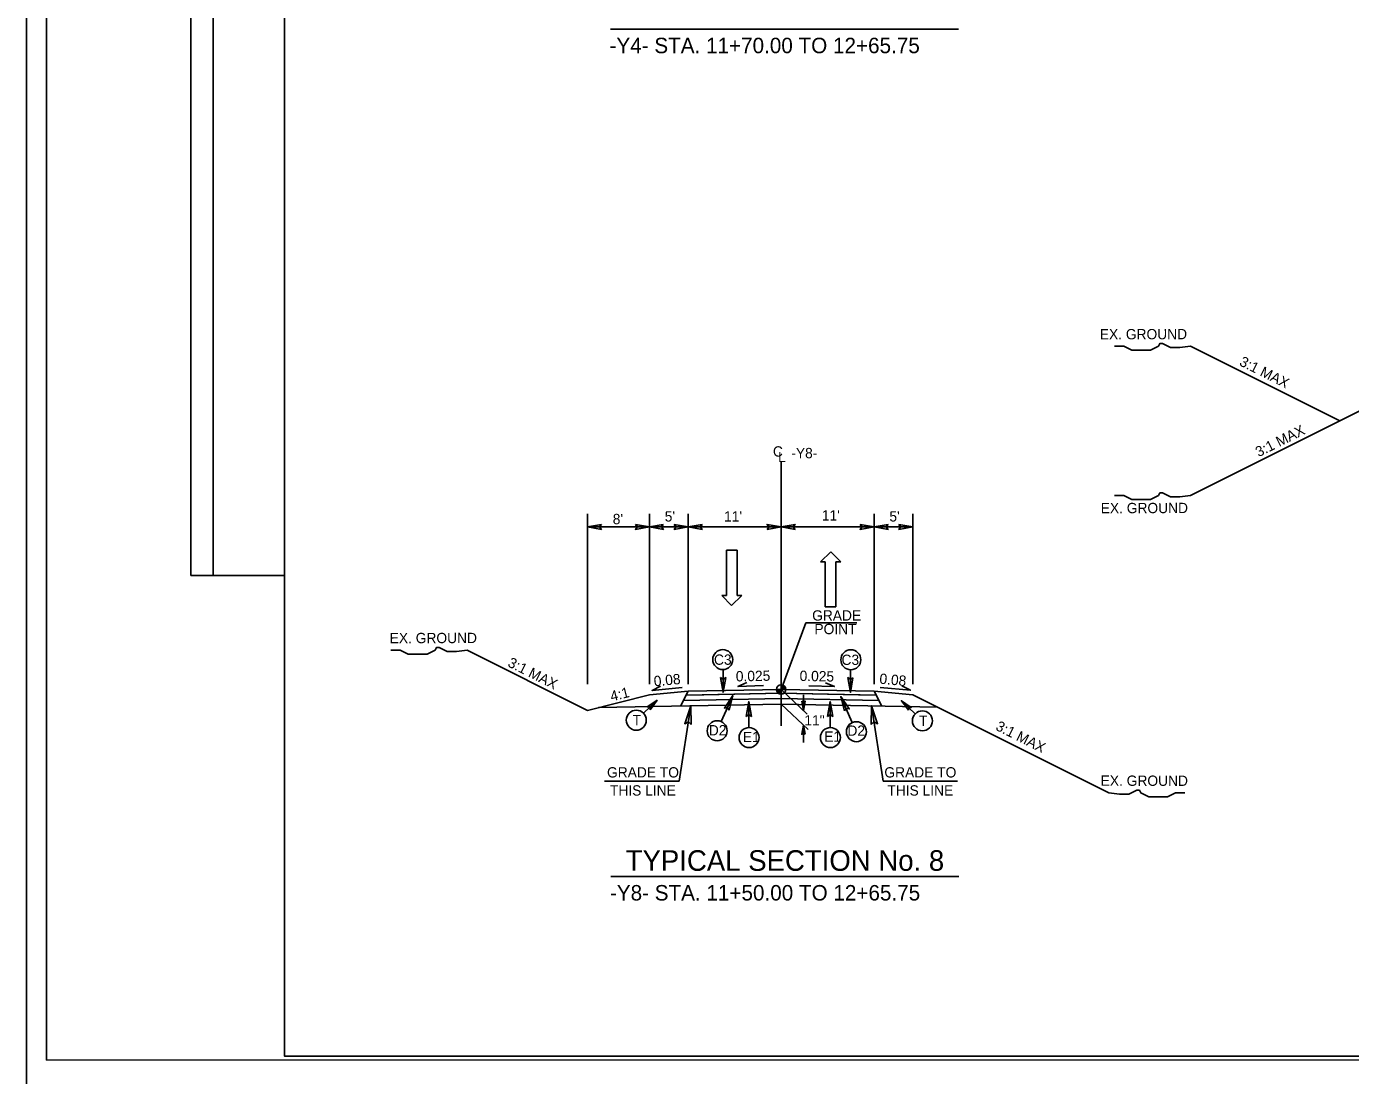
# Model space of a CAD drawing. Extents: x 2320980 to 2456309, y 595047 to 606177.
# Drawn here: x 2455708.8 to 2455879.7, y 596305.6 to 596440.9 of the extents above; entities that cross this region are included whole.
import ezdxf

# ---------------------------------------------------------------- set-up
doc = ezdxf.new("R2010")
doc.units = 0
for name, color, linetype in [('Old_Level_1', 7, 'Continuous'), ('Old_Level_11', 7, 'Continuous'), ('Old_Level_2', 7, 'Continuous'), ('Old_Level_20', 7, 'Continuous'), ('Old_Level_21', 7, 'Continuous'), ('Old_Level_3', 7, 'Continuous'), ('Prop Dimension', 7, 'Continuous'), ('Prop Dimension Text', 7, 'Continuous'), ('Prop Lane Arrow CELL', 7, 'Continuous'), ('Prop Terminator CELL', 7, 'Continuous'), ('Sheet Block Revision CELL', 7, 'Continuous'), ('Sheet Cutting Line CELL', 7, 'Continuous'), ('Sheet Plan CELL', 7, 'Continuous'), ('Sheet Plot Border Inside CELL', 7, 'Continuous'), ('Sheet Plot Border Outside CELL', 7, 'Continuous'), ('Typical Grade Point Symbol CELL', 7, 'Continuous'), ('Typical ID Circle CELL', 7, 'Continuous'), ('Typical Pavement Slope CELL', 7, 'Continuous'), ('Typical Pavement Slope Information CELL', 7, 'Continuous'), ('Typical Slope Point Local CELL', 7, 'Continuous'), ('Typical Terminator CELL', 7, 'Continuous')]:
    doc.layers.add(name, color=color, linetype=linetype)

msp = doc.modelspace()

# ---------------------------------------------------------------- linework, layer by layer
at = {"layer": 'Old_Level_1'}
for p, q in [((2455806.21, 596355.38), (2455809.42, 596363.99)), ((2455809.42, 596363.99), (2455815.97, 596363.99)), ((2455794.22, 596355.14), (2455789.22, 596354.67)), ((2455818.22, 596355.14), (2455823.22, 596354.67))]:
    msp.add_line(p, q, dxfattribs=at)
at = {"layer": 'Old_Level_11'}
for points in [[(2455794.6, 596350.84), (2455794.57, 596353.27), (2455793.77, 596350.95), (2455794.24, 596351.19)], [(2455817.83, 596350.84), (2455817.86, 596353.27), (2455818.66, 596350.95), (2455818.19, 596351.19)]]:
    msp.add_lwpolyline(points, close=True, dxfattribs=at)
at = {"layer": 'Old_Level_21'}
for p, q in [((2455781.22, 596356.06), (2455781.22, 596378.03)), ((2455789.22, 596356.06), (2455789.22, 596378.03)), ((2455794.22, 596356.06), (2455794.22, 596378.03)), ((2455818.22, 596356.06), (2455818.22, 596378.03)), ((2455823.22, 596356.06), (2455823.22, 596378.03)), ((2455781.22, 596376.34), (2455789.22, 596376.34)), ((2455789.22, 596376.34), (2455794.22, 596376.34)), ((2455794.22, 596376.34), (2455806.22, 596376.34)), ((2455818.22, 596376.34), (2455806.22, 596376.34)), ((2455818.22, 596376.34), (2455823.22, 596376.34)), ((2455793.05, 596343.55), (2455794.57, 596353.27)), ((2455819.38, 596343.55), (2455817.86, 596353.27)), ((2455793.05, 596343.55), (2455783.43, 596343.55)), ((2455819.38, 596343.55), (2455829, 596343.55))]:
    msp.add_line(p, q, dxfattribs=at)
at = {"layer": 'Old_Level_3'}
for p, q in [((2455784.21, 596440.56), (2455829.13, 596440.56)), ((2455806.22, 596354.9), (2455793.96, 596354.66)), ((2455806.22, 596354.9), (2455818.47, 596354.66)), ((2455784.25, 596331.25), (2455829.17, 596331.25))]:
    msp.add_line(p, q, dxfattribs=at)
at = {"layer": 'Prop Dimension'}
for p, q in [((2455806.22, 596355.38), (2455809.59, 596352.2)), ((2455809.09, 596354.67), (2455809.09, 596352.67)), ((2455806.21, 596353.5), (2455809.72, 596350.2)), ((2455809.09, 596350.79), (2455809.09, 596348.54))]:
    msp.add_line(p, q, dxfattribs=at)
at = {"layer": 'Prop Dimension Text'}
for p, q in [((2455806.22, 596350.68), (2455806.22, 596384.7)), ((2455788.45, 596352.3), (2455790.21, 596353.99)), ((2455823.51, 596352.23), (2455821.75, 596353.91))]:
    msp.add_line(p, q, dxfattribs=at)
for points in [[(2455793.44, 596355.63), (2455789.55, 596355.25), (2455790.65, 596355.82)], [(2455803.96, 596355.87), (2455800.64, 596355.78), (2455801.78, 596356.27)], [(2455809.77, 596355.85), (2455813.09, 596355.76), (2455811.96, 596356.24)], [(2455819, 596355.64), (2455822.9, 596355.27), (2455821.8, 596355.83)]]:
    msp.add_lwpolyline(points, dxfattribs=at)
for centre in [(2455798.68, 596359.23), (2455815.21, 596359.21), (2455787.52, 596351.41), (2455797.96, 596350.05), (2455815.93, 596349.93), (2455824.45, 596351.33), (2455802.07, 596349.17), (2455812.57, 596349.17)]:
    msp.add_circle(centre, 1.29, dxfattribs=at)
at = {"layer": 'Prop Lane Arrow CELL'}
for p, q in [((2455799.16, 596373.33), (2455799.16, 596367.51)), ((2455800.54, 596373.33), (2455799.16, 596373.33)), ((2455800.54, 596367.51), (2455800.54, 596373.33)), ((2455812.61, 596373.15), (2455811.28, 596371.84)), ((2455811.28, 596371.84), (2455811.91, 596371.84)), ((2455811.91, 596371.84), (2455811.91, 596366.03)), ((2455813.9, 596371.84), (2455812.61, 596373.15)), ((2455813.28, 596366.03), (2455813.28, 596371.84)), ((2455813.28, 596371.84), (2455813.9, 596371.84)), ((2455799.16, 596367.51), (2455798.54, 596367.51)), ((2455798.54, 596367.51), (2455799.83, 596366.2)), ((2455799.83, 596366.2), (2455801.16, 596367.51)), ((2455801.16, 596367.51), (2455800.54, 596367.51)), ((2455811.91, 596366.03), (2455813.28, 596366.03))]:
    msp.add_line(p, q, dxfattribs=at)
at = {"layer": 'Prop Terminator CELL'}
for points in [[(2455808.89, 596353.87), (2455809.09, 596352.67), (2455809.3, 596353.87), (2455809.09, 596353.72)], [(2455809.3, 596349.6), (2455809.09, 596350.79), (2455808.88, 596349.59), (2455809.09, 596349.74)]]:
    msp.add_lwpolyline(points, close=True, dxfattribs=at)
at = {"layer": 'Sheet Block Revision CELL'}
msp.add_line((2455732.91, 596370.08), (2455732.91, 596528.2), dxfattribs=at)
msp.add_lwpolyline([(2455730, 596370.07), (2455730, 596528.2), (2455742.11, 596528.21), (2455742.11, 596370.08)], close=True, dxfattribs=at)
at = {"layer": 'Sheet Cutting Line CELL'}
msp.add_line((2455708.81, 596541.57), (2455708.81, 596322.57), dxfattribs=at)
at = {"layer": 'Sheet Plan CELL'}
for points in [[(2456042.11, 596518.08), (2455742.1, 596518.08), (2455742.1, 596308.08), (2456042.11, 596308.08)], [(2455742.1, 596308.08), (2455742.1, 596518.07), (2456002.1, 596518.08), (2456002.1, 596488.07), (2456042.11, 596488.06), (2456042.11, 596308.08)]]:
    msp.add_lwpolyline(points, close=True, dxfattribs=at)
at = {"layer": 'Sheet Plot Border Inside CELL'}
msp.add_lwpolyline([(2455711.41, 596307.57), (2456044.6, 596307.58), (2456044.61, 596518.57), (2455711.41, 596518.57)], close=True, dxfattribs=at)
at = {"layer": 'Sheet Plot Border Outside CELL'}
msp.add_lwpolyline([(2455708.81, 596303.57), (2456045.51, 596303.57), (2456045.51, 596522.57), (2455708.81, 596522.57)], close=True, dxfattribs=at)
at = {"layer": 'Typical Grade Point Symbol CELL'}
for p, q in [((2455805.62, 596355.38), (2455806.21, 596355.38)), ((2455806.21, 596355.38), (2455806.21, 596355.98)), ((2455806.81, 596355.38), (2455806.21, 596355.38)), ((2455806.21, 596354.79), (2455806.21, 596355.38)), ((2455806.21, 596355.38), (2455806.21, 596354.79))]:
    msp.add_line(p, q, dxfattribs=at)
for points in [[(2455805.62, 596355.38), (2455805.62, 596355.32)], [(2455805.63, 596355.38), (2455805.63, 596355.25)], [(2455805.65, 596355.38), (2455805.65, 596355.2)], [(2455805.66, 596355.38), (2455805.66, 596355.17)], [(2455805.67, 596355.38), (2455805.67, 596355.14)], [(2455805.68, 596355.38), (2455805.68, 596355.12)], [(2455805.69, 596355.38), (2455805.69, 596355.09)], [(2455805.7, 596355.38), (2455805.7, 596355.07)], [(2455805.72, 596355.38), (2455805.72, 596355.05)], [(2455805.73, 596355.38), (2455805.73, 596355.04)], [(2455805.74, 596355.38), (2455805.74, 596355.02)], [(2455805.75, 596355.38), (2455805.75, 596355.01)], [(2455805.76, 596355.38), (2455805.76, 596354.99)], [(2455805.78, 596355.38), (2455805.78, 596354.98)], [(2455805.79, 596355.38), (2455805.79, 596354.97)], [(2455805.8, 596355.38), (2455805.8, 596354.95)], [(2455805.81, 596355.38), (2455805.81, 596354.94)], [(2455805.82, 596355.38), (2455805.82, 596354.93)], [(2455805.84, 596355.38), (2455805.84, 596354.92)], [(2455805.85, 596355.38), (2455805.85, 596354.91)], [(2455805.86, 596355.38), (2455805.86, 596354.9)], [(2455805.87, 596355.38), (2455805.87, 596354.9)], [(2455805.88, 596355.38), (2455805.88, 596354.89)], [(2455805.9, 596355.38), (2455805.9, 596354.88)], [(2455805.91, 596355.38), (2455805.91, 596354.87)], [(2455805.92, 596355.38), (2455805.92, 596354.86)], [(2455805.93, 596355.38), (2455805.93, 596354.86)], [(2455805.94, 596355.38), (2455805.94, 596354.85)], [(2455805.95, 596355.38), (2455805.95, 596354.85)], [(2455805.97, 596355.38), (2455805.97, 596354.84)], [(2455805.98, 596355.38), (2455805.98, 596354.84)], [(2455805.99, 596355.38), (2455805.99, 596354.83)], [(2455806, 596355.38), (2455806, 596354.83)], [(2455806.01, 596355.38), (2455806.01, 596354.82)], [(2455806.03, 596355.38), (2455806.03, 596354.82)], [(2455806.04, 596355.38), (2455806.04, 596354.81)], [(2455806.05, 596355.38), (2455806.05, 596354.81)], [(2455806.06, 596355.38), (2455806.06, 596354.81)], [(2455806.07, 596355.38), (2455806.07, 596354.8)], [(2455806.09, 596355.38), (2455806.09, 596354.8)], [(2455806.1, 596355.38), (2455806.1, 596354.8)], [(2455806.11, 596355.38), (2455806.11, 596354.8)], [(2455806.12, 596355.38), (2455806.12, 596354.79)], [(2455806.13, 596355.38), (2455806.13, 596354.79)], [(2455806.15, 596355.38), (2455806.15, 596354.79)], [(2455806.16, 596355.38), (2455806.16, 596354.79)], [(2455806.17, 596355.38), (2455806.17, 596354.79)], [(2455806.18, 596355.38), (2455806.18, 596354.79)], [(2455806.19, 596355.38), (2455806.19, 596354.79)], [(2455806.2, 596355.38), (2455806.2, 596354.79), (2455806.2, 596354.79)], [(2455806.22, 596355.98), (2455806.22, 596355.98), (2455806.22, 596355.38)], [(2455806.23, 596355.98), (2455806.23, 596355.38)], [(2455806.24, 596355.98), (2455806.24, 596355.38)], [(2455806.26, 596355.98), (2455806.26, 596355.38)], [(2455806.27, 596355.97), (2455806.27, 596355.38)], [(2455806.28, 596355.97), (2455806.28, 596355.38)], [(2455806.29, 596355.97), (2455806.29, 596355.38)], [(2455806.3, 596355.97), (2455806.3, 596355.38)], [(2455806.31, 596355.97), (2455806.31, 596355.38)], [(2455806.33, 596355.97), (2455806.33, 596355.38)], [(2455806.34, 596355.96), (2455806.34, 596355.38)], [(2455806.35, 596355.96), (2455806.35, 596355.38)], [(2455806.36, 596355.96), (2455806.36, 596355.38)], [(2455806.37, 596355.95), (2455806.37, 596355.38)], [(2455806.39, 596355.95), (2455806.39, 596355.38)], [(2455806.4, 596355.95), (2455806.4, 596355.38)], [(2455806.41, 596355.94), (2455806.41, 596355.38)], [(2455806.42, 596355.94), (2455806.42, 596355.38)], [(2455806.43, 596355.94), (2455806.43, 596355.38)], [(2455806.45, 596355.93), (2455806.45, 596355.38)], [(2455806.46, 596355.92), (2455806.46, 596355.38)], [(2455806.47, 596355.92), (2455806.47, 596355.38)], [(2455806.48, 596355.91), (2455806.48, 596355.38)], [(2455806.49, 596355.91), (2455806.49, 596355.38)], [(2455806.51, 596355.9), (2455806.51, 596355.38)], [(2455806.52, 596355.89), (2455806.52, 596355.38)], [(2455806.53, 596355.89), (2455806.53, 596355.38)], [(2455806.54, 596355.88), (2455806.54, 596355.38)], [(2455806.55, 596355.87), (2455806.55, 596355.38)], [(2455806.56, 596355.86), (2455806.56, 596355.38)], [(2455806.58, 596355.85), (2455806.58, 596355.38)], [(2455806.59, 596355.85), (2455806.59, 596355.38)], [(2455806.6, 596355.83), (2455806.6, 596355.38)], [(2455806.61, 596355.82), (2455806.61, 596355.38)], [(2455806.62, 596355.81), (2455806.62, 596355.38)], [(2455806.64, 596355.8), (2455806.64, 596355.38)], [(2455806.65, 596355.79), (2455806.65, 596355.38)], [(2455806.66, 596355.78), (2455806.66, 596355.38)], [(2455806.67, 596355.76), (2455806.67, 596355.38)], [(2455806.68, 596355.75), (2455806.68, 596355.38)], [(2455806.7, 596355.73), (2455806.7, 596355.38)], [(2455806.71, 596355.71), (2455806.71, 596355.38)], [(2455806.72, 596355.7), (2455806.72, 596355.38)], [(2455806.73, 596355.68), (2455806.73, 596355.38)], [(2455806.74, 596355.65), (2455806.74, 596355.38)], [(2455806.76, 596355.63), (2455806.76, 596355.38)], [(2455806.77, 596355.6), (2455806.77, 596355.38)], [(2455806.78, 596355.57), (2455806.78, 596355.38)], [(2455806.79, 596355.53), (2455806.79, 596355.38)], [(2455806.8, 596355.47), (2455806.8, 596355.38)]]:
    msp.add_lwpolyline(points, dxfattribs=at)
msp.add_circle((2455806.21, 596355.38), 0.595, dxfattribs=at)
for start, end in [(179.9905, 269.9905), (359.9905, 89.9905)]:
    msp.add_arc((2455806.21, 596355.38), 0.595, start, end, dxfattribs=at)
at = {"layer": 'Typical ID Circle CELL'}
for p, q in [((2455798.73, 596357.95), (2455798.73, 596355.01)), ((2455815.16, 596357.94), (2455815.16, 596355)), ((2455798.48, 596351.24), (2455799.97, 596354.54)), ((2455802.04, 596350.47), (2455802.04, 596353.81)), ((2455812.54, 596350.47), (2455812.54, 596353.81)), ((2455815.4, 596351.12), (2455813.92, 596354.42))]:
    msp.add_line(p, q, dxfattribs=at)
at = {"layer": 'Typical Pavement Slope CELL'}
for p, q in [((2455793.23, 596353.24), (2455794.22, 596355.14)), ((2455793.96, 596354.66), (2455793.61, 596353.97)), ((2455794.22, 596355.14), (2455793.96, 596354.66)), ((2455793.96, 596354.66), (2455806.22, 596354.9)), ((2455796.22, 596354.7), (2455793.96, 596354.66)), ((2455806.22, 596355.38), (2455794.22, 596355.14)), ((2455806.22, 596355.38), (2455794.22, 596355.14)), ((2455806.22, 596354.9), (2455796.22, 596354.7)), ((2455806.22, 596355.38), (2455818.22, 596355.14)), ((2455806.22, 596355.38), (2455818.22, 596355.14)), ((2455806.22, 596354.9), (2455806.22, 596355.38)), ((2455806.22, 596354.9), (2455806.22, 596355.38)), ((2455818.47, 596354.66), (2455806.22, 596354.9)), ((2455806.22, 596354.9), (2455806.22, 596354.22)), ((2455806.22, 596354.22), (2455806.22, 596354.9)), ((2455818.22, 596355.14), (2455818.47, 596354.66)), ((2455819.2, 596353.24), (2455818.22, 596355.14)), ((2455818.82, 596353.97), (2455818.47, 596354.66)), ((2455806.22, 596353.5), (2455782.64, 596353.03)), ((2455806.22, 596354.22), (2455793.61, 596353.97)), ((2455793.61, 596353.97), (2455806.22, 596354.22)), ((2455806.22, 596354.22), (2455818.82, 596353.97)), ((2455806.22, 596354.22), (2455818.82, 596353.97)), ((2455806.22, 596353.5), (2455826.36, 596353.1))]:
    msp.add_line(p, q, dxfattribs=at)
msp.add_lwpolyline([(2455818.47, 596354.66), (2455816.22, 596354.7), (2455806.22, 596354.9)], dxfattribs=at)
at = {"layer": 'Typical Slope Point Local CELL'}
for p, q in [((2455878.35, 596390.03), (2455859.06, 596399.68)), ((2455859.06, 596380.39), (2455884.35, 596393.03)), ((2455765.68, 596360.44), (2455781.22, 596352.67)), ((2455789.22, 596354.67), (2455781.22, 596352.67)), ((2455848.5, 596342.03), (2455823.22, 596354.67))]:
    msp.add_line(p, q, dxfattribs=at)
for points in [[(2455859.06, 596399.68), (2455857.68, 596399.5), (2455857.34, 596399.5), (2455856.82, 596399.5), (2455856.48, 596399.5), (2455856.13, 596399.68), (2455855.79, 596399.85), (2455855.44, 596400.02), (2455855.1, 596400.02), (2455854.92, 596399.68), (2455854.58, 596399.5), (2455854.23, 596399.33), (2455853.89, 596399.16), (2455853.54, 596399.16), (2455853.2, 596399.16), (2455852.85, 596399.16), (2455852.51, 596399.16), (2455852.16, 596399.16), (2455851.82, 596399.16), (2455851.47, 596399.16), (2455851.13, 596399.33), (2455850.78, 596399.5), (2455850.44, 596399.68), (2455849.92, 596399.68), (2455849.58, 596399.68), (2455849.23, 596399.68)], [(2455859.06, 596380.39), (2455857.68, 596380.22), (2455857.34, 596380.22), (2455856.82, 596380.22), (2455856.48, 596380.22), (2455856.13, 596380.39), (2455855.79, 596380.56), (2455855.44, 596380.74), (2455855.1, 596380.74), (2455854.92, 596380.39), (2455854.58, 596380.22), (2455854.23, 596380.05), (2455853.89, 596379.87), (2455853.54, 596379.87), (2455853.2, 596379.87), (2455852.85, 596379.87), (2455852.51, 596379.87), (2455852.16, 596379.87), (2455851.82, 596379.87), (2455851.47, 596379.87), (2455851.13, 596380.05), (2455850.78, 596380.22), (2455850.44, 596380.39), (2455849.92, 596380.39), (2455849.58, 596380.39), (2455849.23, 596380.39)], [(2455765.68, 596360.44), (2455764.3, 596360.27), (2455763.96, 596360.27), (2455763.44, 596360.27), (2455763.09, 596360.27), (2455762.75, 596360.44), (2455762.4, 596360.61), (2455762.06, 596360.79), (2455761.72, 596360.79), (2455761.54, 596360.44), (2455761.2, 596360.27), (2455760.85, 596360.09), (2455760.51, 596359.92), (2455760.16, 596359.92), (2455759.82, 596359.92), (2455759.47, 596359.92), (2455759.13, 596359.92), (2455758.78, 596359.92), (2455758.44, 596359.92), (2455758.09, 596359.92), (2455757.75, 596360.09), (2455757.4, 596360.27), (2455757.06, 596360.44), (2455756.54, 596360.44), (2455756.2, 596360.44), (2455755.85, 596360.44)], [(2455848.5, 596342.03), (2455849.88, 596341.86), (2455850.22, 596341.86), (2455850.74, 596341.86), (2455851.09, 596341.86), (2455851.43, 596342.03), (2455851.78, 596342.2), (2455852.12, 596342.38), (2455852.47, 596342.38), (2455852.64, 596342.03), (2455852.98, 596341.86), (2455853.33, 596341.68), (2455853.67, 596341.51), (2455854.02, 596341.51), (2455854.36, 596341.51), (2455854.71, 596341.51), (2455855.05, 596341.51), (2455855.4, 596341.51), (2455855.74, 596341.51), (2455856.09, 596341.51), (2455856.43, 596341.68), (2455856.78, 596341.86), (2455857.12, 596342.03), (2455857.64, 596342.03), (2455857.99, 596342.03), (2455858.33, 596342.03)]]:
    msp.add_lwpolyline(points, dxfattribs=at)
at = {"layer": 'Typical Terminator CELL'}
for points in [[(2455783.01, 596376.65), (2455781.22, 596376.34), (2455783.02, 596376.02), (2455782.79, 596376.34)], [(2455787.42, 596376.65), (2455789.22, 596376.34), (2455787.41, 596376.02), (2455787.64, 596376.34)], [(2455791.01, 596376.65), (2455789.22, 596376.34), (2455791.02, 596376.02), (2455790.79, 596376.34)], [(2455792.42, 596376.65), (2455794.22, 596376.34), (2455792.41, 596376.02), (2455792.64, 596376.34)], [(2455796.01, 596376.65), (2455794.22, 596376.34), (2455796.02, 596376.02), (2455795.79, 596376.34)], [(2455804.42, 596376.03), (2455806.22, 596376.34), (2455804.41, 596376.66), (2455804.64, 596376.34)], [(2455808.01, 596376.03), (2455806.22, 596376.34), (2455808.02, 596376.66), (2455807.79, 596376.34)], [(2455816.42, 596376.65), (2455818.22, 596376.34), (2455816.41, 596376.02), (2455816.64, 596376.34)], [(2455820.01, 596376.65), (2455818.22, 596376.34), (2455820.02, 596376.02), (2455819.79, 596376.34)], [(2455821.42, 596376.65), (2455823.22, 596376.34), (2455821.41, 596376.02), (2455821.64, 596376.34)], [(2455798.4, 596356.91), (2455798.73, 596355.01), (2455799.06, 596356.92), (2455798.73, 596356.68)], [(2455815.49, 596356.89), (2455815.16, 596355), (2455814.83, 596356.9), (2455815.16, 596356.66)], [(2455789.3, 596352.76), (2455790.21, 596353.99), (2455788.94, 596353.14), (2455789.26, 596353.08)], [(2455799.5, 596352.72), (2455799.98, 596354.58), (2455798.89, 596352.98), (2455799.3, 596353.06)], [(2455801.72, 596351.91), (2455802.04, 596353.81), (2455802.38, 596351.9), (2455802.04, 596352.14)], [(2455812.21, 596351.91), (2455812.54, 596353.81), (2455812.88, 596351.9), (2455812.54, 596352.14)], [(2455814.39, 596352.6), (2455813.91, 596354.46), (2455815, 596352.86), (2455814.59, 596352.94)], [(2455822.66, 596352.69), (2455821.75, 596353.91), (2455823.02, 596353.06), (2455822.7, 596353)]]:
    msp.add_lwpolyline(points, close=True, dxfattribs=at)

# ---------------------------------------------------------------- texts
at = {"layer": 'Old_Level_1'}
for rotation, p in [(0.0897, (2455847.35, 596400.54)), (0.0897, (2455847.47, 596378.11)), (0.0897, (2455755.69, 596361.34)), (359.9103, (2455847.46, 596342.95))]:
    msp.add_text('EX. GROUND', height=1.33, rotation=rotation, dxfattribs=at).set_placement(p)
for s, p in [('GRADE', (2455810.22, 596364.26)), ('POINT', (2455810.51, 596362.51))]:
    msp.add_text(s, height=1.33, dxfattribs=at).set_placement(p)
at = {"layer": 'Old_Level_2'}
for s, height, p in [('-Y4- STA. 11+70.00 TO 12+65.75', 1.995, (2455784.07, 596437.46)), ('TYPICAL SECTION No. 8', 2.66, (2455786.15, 596331.98)), ('-Y8- STA. 11+50.00 TO 12+65.75', 1.995, (2455784.12, 596328.15))]:
    msp.add_text(s, height=height, dxfattribs=at).set_placement(p)
at = {"layer": 'Old_Level_20'}
for s, p in [('C3', (2455797.55, 596358.56)), ('C3', (2455814.01, 596358.54)), ('T', (2455787.05, 596350.75)), ('T', (2455824.01, 596350.67)), ('D2', (2455796.88, 596349.45)), ('E1', (2455801.28, 596348.58)), ('E1', (2455811.78, 596348.64)), ('D2', (2455814.77, 596349.4))]:
    msp.add_text(s, height=1.33, dxfattribs=at).set_placement(p)
at = {"layer": 'Old_Level_21'}
for s, rotation, p in [('3:1 MAX', 333.4341, (2455865.26, 596397.24)), ('3:1 MAX', 26.5659, (2455867.85, 596385.33)), ('C', 0.0002, (2455805.16, 596385.42)), ('L', 0.0002, (2455805.82, 596384.7)), ('3:1 MAX', 333.4349, (2455770.82, 596358.4)), ('0.08', 5.3417, (2455789.84, 596355.77)), ('0.025', 1.1456, (2455800.38, 596356.41)), ('0.025', 358.8544, (2455808.59, 596356.48)), ('0.08', 354.6583, (2455818.86, 596356.13)), ('3:1 MAX', 333.4341, (2455833.8, 596350.21))]:
    msp.add_text(s, height=1.33, rotation=rotation, dxfattribs=at).set_placement(p)
for s, p in [('-Y8-', (2455807.53, 596385.21)), ("8'", (2455784.48, 596376.7)), ("5'", (2455791.19, 596377.04)), ("11'", (2455798.85, 596377.04)), ("11'", (2455811.47, 596377.17)), ("5'", (2455820.19, 596377.04)), ('GRADE TO', (2455783.74, 596344.02)), ('GRADE TO', (2455819.54, 596344.02)), ('THIS LINE', (2455784.12, 596341.69)), ('THIS LINE', (2455819.93, 596341.69))]:
    msp.add_text(s, height=1.33, dxfattribs=at).set_placement(p)
at = {"layer": 'Typical Pavement Slope Information CELL'}
msp.add_text('11"', height=1.33, dxfattribs=at).set_placement((2455809.22, 596350.73))
at = {"layer": 'Typical Slope Point Local CELL'}
msp.add_text('4:1', height=1.33, rotation=14.0362, dxfattribs=at).set_placement((2455784.34, 596353.82))

doc.saveas('drawing.dxf')
